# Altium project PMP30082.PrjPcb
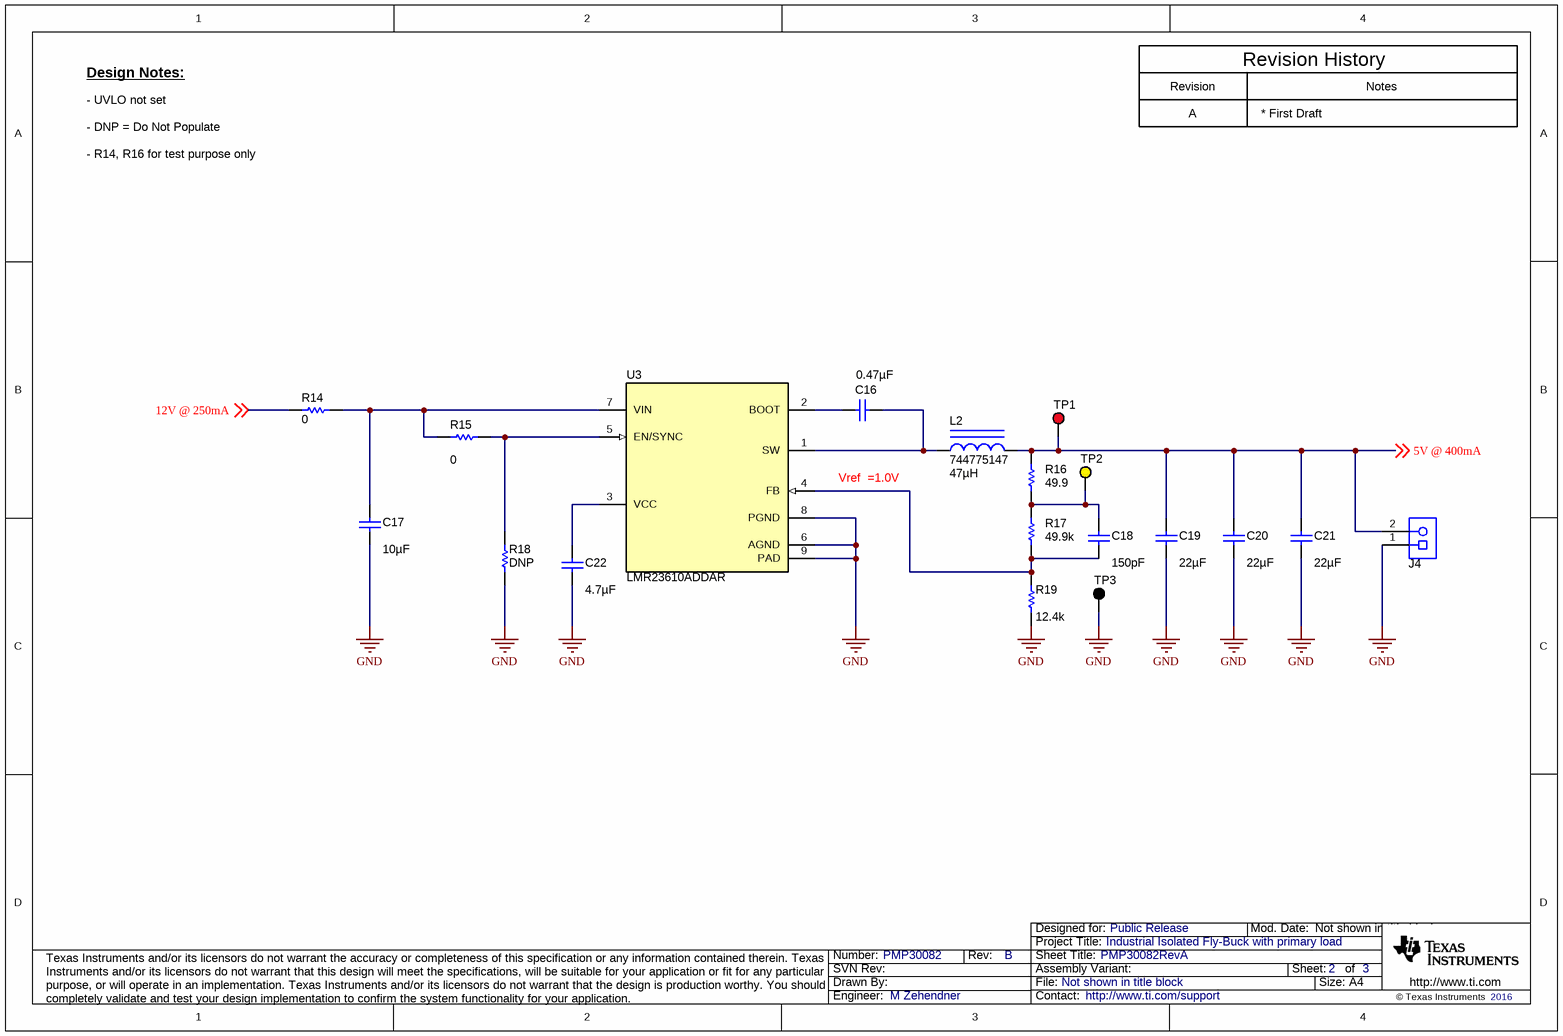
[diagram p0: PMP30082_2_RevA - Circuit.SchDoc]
CopyrightYear: 2016; EVM_Orderable: N/A; PCB_Layout: Who did the Layout?; PCB_Rev: A; PRJ_Customer: Public Release; PRJ_Engineer: M Zehendner; PRJ_Number: PMP30082; PRJ_Title: Industrial Isolated Fly-Buck with primary load; SCH_Rev: B; TechSupport: http://www.ti.com/support
3 sheets, 56 parts. Net scope: global (net labels, ports and power ports of the same name join across sheets).
Board file: PMP30082.PcbDoc
Sheets:
  PMP30082_2_RevA - Circuit.SchDoc
  PMP30082_3_RevA - Circuit.SchDoc
  PMP30082_1_RevB - Circuit.SchDoc

## Sheet PMP30082_2_RevA - Circuit.SchDoc: PMP30082RevA
size A4; Date: Not shown in title block; ApprovedBy: Not shown in title block; CheckedBy: Not shown in title block; Author: Not shown in title block; CompanyName: Not shown in title block; Engineer: Not shown in title block; Organization: Not shown in title block; Address1: Not shown in title block; Address2: Not shown in title block; Address3: Not shown in title block; Address4: Not shown in title block; DocumentNumber: 2; Revision: Use project parameter SCH_Rev; SheetNumber: 2; SheetTotal: 3; PageSetup: Record=PageOptions¦CenterHorizontal=True¦CenterVertical=True¦PrintScale=0.97¦XCorrection=1.00¦YCorrection=1.00¦PrintKind=0¦BorderSize=5000000¦LeftOffset=0¦BottomOffset=0¦Orientation=2¦PaperLength=1000¦PaperWidth=1000¦Scale=100¦PaperSource=15¦PrintQuality=600¦MediaType=1¦DitherType=10¦PaperKind=A4¦PrintScaleMode=1

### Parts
C16  ValueDisplayed: 0.47µF  [0603]  (hidden comment: GRM188R71C474KA88D)
C17  ValueDisplayed: 10µF  [0805_HV]  (hidden comment: GRM21BC71E106KE11L)
C18  ValueDisplayed: 150pF  [0603]  (hidden comment: GRM1885C2A151JA01D)
C19  ValueDisplayed: 22µF  [0805_HV]  (hidden comment: GRM21BR61A226ME44L)
C20  ValueDisplayed: 22µF  [0805_HV]  (hidden comment: GRM21BR61A226ME44L)
C21  ValueDisplayed: 22µF  [0805_HV]  (hidden comment: GRM21BR61A226ME44L)
C22  ValueDisplayed: 4.7µF  [0805_HV]  (hidden comment: GRM21BR71C475KA73L)
J4  691 101 710 002  [Wurth_691101710002]  (value not drawn)
L2  744775147  ValueDisplayed: 47µH  [WE-PD2-L]
R14  ValueDisplayed: 0  [0603]  (hidden comment: ERJ-3GEY0R00V)
R15  ValueDisplayed: 0  [0603]  (hidden comment: ERJ-3GEY0R00V)
R16  ValueDisplayed: 49.9  [0603]  (hidden comment: CRCW060349R9FKEA)
R17  ValueDisplayed: 49.9k  [0603]  (hidden comment: CRCW060349K9FKEA)
R18  ValueDisplayed: DNP  [0603]  (hidden comment: ERJ-3GEY0R00V)
R19  ValueDisplayed: 12.4k  [0603]  (hidden comment: CRCW060312K4FKEA)
TP1  5010  [Keystone5010]  (value not drawn)
TP2  5014  [Keystone5014]  (value not drawn)
TP3  5011  [Keystone5011]  (value not drawn)
U3  LMR23610ADDAR  [DDA0008E_N]

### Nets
GND: C17.2 C19.2 C20.2 C21.2 C22.2 J4.1 R18.1 R19.1 TP3.1 U3.6(AGND) U3.8(PGND) U3.9(PAD)
5V @ 400mA: C19.1 C20.1 C21.1 J4.2 L2.2 R16.2 TP1.1 ; off-sheet 5V @ 400mA
12V @ 250mA: R14.2 ; off-sheet 12V @ 250mA
NetC16_1: C16.1 L2.1 U3.1(SW)
NetC16_2: C16.2 U3.2(BOOT)
NetC17_1: C17.1 R14.1 R15.1 U3.7(VIN)
NetC18_1: C18.1 R16.1 R17.2 TP2.1
NetC18_2: C18.2 R17.1 R19.2 U3.4(FB)
NetC22_1: C22.1 U3.3(VCC)
NetR15_2: R15.2 R18.2 U3.5(EN/SYNC)

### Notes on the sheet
- Design Notes:
- - UVLO not set
- Revision
- A
- * First Draft
- Revision History
- Notes
- - DNP = Do Not Populate
- - R14, R16 for test purpose only
- Vref  =1.0V

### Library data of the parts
C16 = GRM188R71C474KA88D: CAP, CERM, 0.47 µF, 16 V, +/- 10%, X7R, 0603; Manufacturer: MuRata; Polarized: N; CompType: Capacitor; Value: 0.47uF; U/M: EA; Cap_F: 0.00000047; Tolerance_%: 10; Value1: Unknown; VDC_V: 16; Value2: 16V; TaMin_C: -55; TaMax_C: 125; SizeArea_mm2: 1.28; SizeAreaWB_mm2: 4.68; SizeX_mm: 1.6; SizeY_mm: 0.8; SizeZ_mm: 1; AEC Category: Q200
C17 = GRM21BC71E106KE11L: CAP, CERM, 10 µF, 25 V, +/- 10%, X7S, 0805; Manufacturer: MuRata; Polarized: N; CompType: Capacitor; Value: 10uF; U/M: EA; Cap_F: 0.00001; Tolerance_%: 10; Value1: Unknown; VDC_V: 25; Value2: 25V; TaMin_C: -55; TaMax_C: 125; Cap_Case: 0805; SizeArea_mm2: 2.5; SizeAreaWB_mm2: 6.75; SizeX_mm: 2; SizeY_mm: 1.25; SizeZ_mm: 1.45; AEC Category: Q200
C18 = GRM1885C2A151JA01D: CAP, CERM, 150 pF, 100 V, +/- 5%, C0G/NP0, 0603; Manufacturer: MuRata; Polarized: N; CompType: Capacitor; Value: 150pF; U/M: EA; Cap_F: 0.00000000015; Tolerance_%: 5; Value1: Unknown; VDC_V: 100; Value2: 100V; TaMin_C: -55; TaMax_C: 125; SizeArea_mm2: 1.28; SizeAreaWB_mm2: 4.68; SizeX_mm: 1.6; SizeY_mm: 0.8; SizeZ_mm: 1; AEC Category: Q200
C19-C21 = GRM21BR61A226ME44L: CAP, CERM, 22 µF, 10 V, +/- 20%, X5R, 0805; Manufacturer: MuRata; Polarized: N; CompType: Capacitor; Value: 22uF; U/M: EA; Cap_F: 0.000022; Tolerance_%: 20; Value1: Unknown; VDC_V: 10; Value2: 10V; TaMin_C: -55; TaMax_C: 85; Cap_Case: 0805; SizeArea_mm2: 2.5; SizeAreaWB_mm2: 6.75; SizeX_mm: 2; SizeY_mm: 1.25; SizeZ_mm: 1.45; AEC Category: Q200
C22 = GRM21BR71C475KA73L: CAP, CERM, 4.7 µF, 16 V, +/- 10%, X7R, 0805; Manufacturer: MuRata; Polarized: N; CompType: Capacitor; Value: 4.7uF; U/M: EA; Cap_F: 0.0000047; Tolerance_%: 10; ESR_ohm: 0.006; Value1: 0.006 ohm; VDC_V: 16; Value2: 16V; TaMin_C: -55; TaMax_C: 125; Cap_Case: 0805; SizeArea_mm2: 2.5; SizeAreaWB_mm2: 6.75; SizeX_mm: 2; SizeY_mm: 1.25; SizeZ_mm: 1.45; AEC Category: Q200
J4 = 691 101 710 002: Terminal Block, 5 mm, 2x1, Tin, TH; Manufacturer: Wurth Elektronik; SymbolCreator: a0412235
L2 = 744775147: Inductor, Shielded Drum Core, Ferrite, 47 µH, 1.17 A, 0.18 ohm, SMD; Manufacturer: Wurth Elektronik; Value: 47uH; Ind_H: 47.0E-6; Imax_A: 1.17; Irms: 1.17A @ 40C rise; Isat: 1.24A @ 10% inductance drop; DCR_ohm: 0.18; Value2: 1.17A; AEC Category: Q200
R14 R15 R18 = ERJ-3GEY0R00V: RES, 0, 5%, 0.1 W, 0603; Manufacturer: Panasonic; CompType: Resistor; Value: 0; Value_Code: 0000; Tolerance_%: 5; Power_W: 0.1; Value2: 0.1W; VDC_V: 50; TempCo: 600 ppm/C; SizeArea_mm2: 1.28; SizeX_mm: 1.6; SizeY_mm: 0.8; SizeZ_mm: 1; EIA_Code: E24; U/M: EA; AEC Category: Q200
R16 = CRCW060349R9FKEA: RES, 49.9, 1%, 0.1 W, 0603; Manufacturer: Vishay-Dale; CompType: Resistor; Value: 49.9; Value_Code: 49R9; Tolerance_%: 1; Power_W: 0.1; Value2: 0.1W; VDC_V: 75; TempCo: 100 ppm/C; SizeArea_mm2: 1.28; SizeX_mm: 1.6; SizeY_mm: 0.8; EIA_Code: E96; U/M: EA; AEC Category: Q200
R17 = CRCW060349K9FKEA: RES, 49.9 k, 1%, 0.1 W, 0603; Manufacturer: Vishay-Dale; CompType: Resistor; Value: 49.9k; Res_ohm: 49900; Value_Code: 49k9; Tolerance_%: 1; Power_W: 0.1; Value2: 0.1W; VDC_V: 75; TempCo: 100 ppm/C; SizeArea_mm2: 1.28; SizeX_mm: 1.6; SizeY_mm: 0.8; EIA_Code: E96; U/M: EA; AEC Category: Q200
R19 = CRCW060312K4FKEA: RES, 12.4 k, 1%, 0.1 W, 0603; Manufacturer: Vishay-Dale; CompType: Resistor; Value: 12.4k; Res_ohm: 12400; Value_Code: 12k4; Tolerance_%: 1; Power_W: 0.1; Value2: 0.1W; VDC_V: 75; TempCo: 100 ppm/C; SizeArea_mm2: 1.28; SizeX_mm: 1.6; SizeY_mm: 0.8; EIA_Code: E96; U/M: EA; AEC Category: Q200
TP1 = 5010: Test Point, Multipurpose, Red, TH; Manufacturer: Keystone; CompType: Test Point Loop; ContactFinish: Silver
TP2 = 5014: Test Point, Multipurpose, Yellow, TH; Manufacturer: Keystone; CompType: Test Point Loop; ContactFinish: Silver
TP3 = 5011: Test Point, Multipurpose, Black, TH; Manufacturer: Keystone; CompType: Test Point Loop; ContactFinish: Silver
U3 = LMR23610ADDAR: SIMPLE SWITCHER 36 V, 1 A Synchronous Step-Down Converter, DDA0008E; Manufacturer: Texas Instruments; SymbolCreator: a0411947; SizeArea_mm2: 31; SizeAreaWB_mm2: 57.4; SizeX_mm: 5; SizeY_mm: 6.2; SizeZ_mm: 1.7; CompType: IC; U/M: EA

## Sheet PMP30082_3_RevA - Circuit.SchDoc: PMP30082RevA
size A4; Date: Not shown in title block; ApprovedBy: Not shown in title block; CheckedBy: Not shown in title block; Author: Not shown in title block; CompanyName: Not shown in title block; Engineer: Not shown in title block; Organization: Not shown in title block; Address1: Not shown in title block; Address2: Not shown in title block; Address3: Not shown in title block; Address4: Not shown in title block; DocumentNumber: 3; Revision: Use project parameter SCH_Rev; SheetNumber: 3; SheetTotal: 3; PageSetup: Record=PageOptions¦CenterHorizontal=True¦CenterVertical=True¦PrintScale=0.97¦XCorrection=1.00¦YCorrection=1.00¦PrintKind=0¦BorderSize=5000000¦LeftOffset=0¦BottomOffset=0¦Orientation=2¦PaperLength=1000¦PaperWidth=1000¦Scale=100¦PaperSource=15¦PrintQuality=600¦MediaType=1¦DitherType=10¦PaperKind=A4¦PrintScaleMode=1
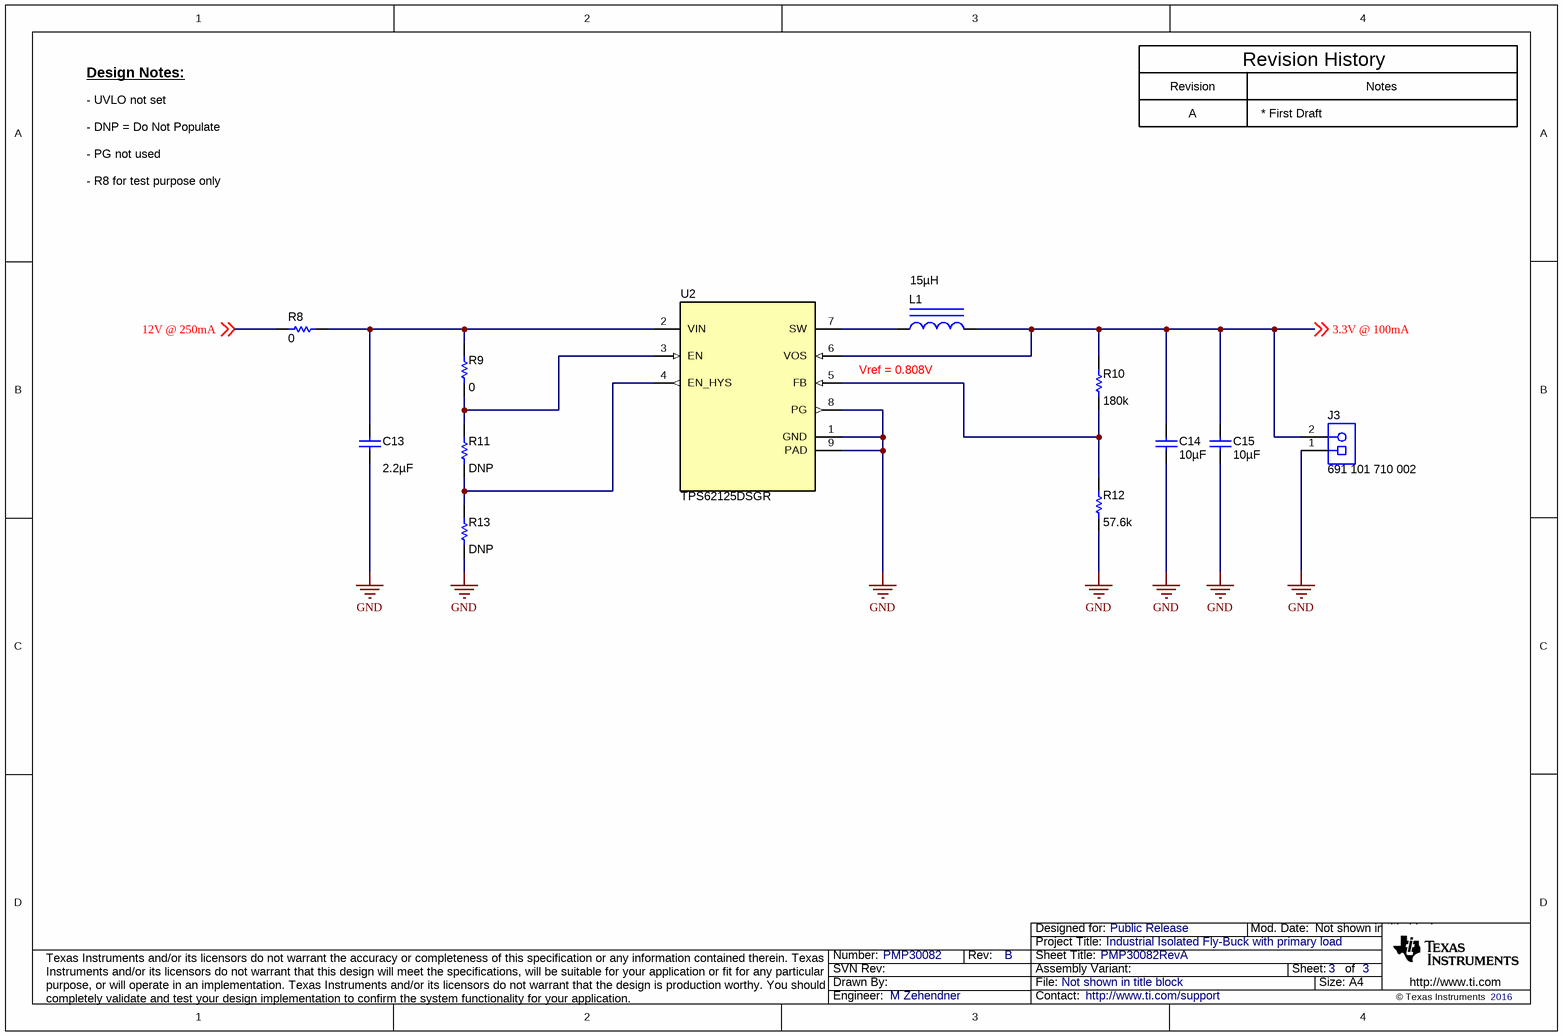
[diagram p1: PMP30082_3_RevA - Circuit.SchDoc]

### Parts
C13  ValueDisplayed: 2.2µF  [0805_HV]  (hidden comment: GRM21BR61E225KA12L)
C14  ValueDisplayed: 10µF  [0805_HV]  (hidden comment: GRM21BR70J106KE76L)
C15  ValueDisplayed: 10µF  [0805_HV]  (hidden comment: GRM21BR70J106KE76L)
J3  691 101 710 002  [Wurth_691101710002]
L1  ValueDisplayed: 15µH  [VLF302515MT]  (hidden comment: VLF302515MT-150M)
R8  ValueDisplayed: 0  [0603]  (hidden comment: ERJ-3GEY0R00V)
R9  ValueDisplayed: 0  [0603]  (hidden comment: ERJ-3GEY0R00V)
R10  ValueDisplayed: 180k  [0603]  (hidden comment: CRCW0603180KJNEA)
R11  ValueDisplayed: DNP  [0603]  (hidden comment: ERJ-3GEY0R00V)
R12  ValueDisplayed: 57.6k  [0603]  (hidden comment: CRCW060357K6FKEA)
R13  ValueDisplayed: DNP  [0603]  (hidden comment: ERJ-3GEY0R00V)
U2  TPS62125DSGR  [DSG0008A]

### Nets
GND: C13.2 C14.2 C15.2 J3.1 R12.1 R13.1 U2.1(GND) U2.8(PG) U2.9(PAD)
3.3V @ 100mA: C14.1 C15.1 J3.2 L1.2 R10.2 U2.6(VOS) ; off-sheet 3.3V @ 100mA
12V @ 250mA: R8.2 ; off-sheet 12V @ 250mA
NetC13_1: C13.1 R8.1 R9.2 U2.2(VIN)
NetL1_1: L1.1 U2.7(SW)
NetR9_1: R9.1 R11.2 U2.3(EN)
NetR10_1: R10.1 R12.2 U2.5(FB)
NetR11_1: R11.1 R13.2 U2.4(EN_HYS)

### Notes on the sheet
- Design Notes:
- - UVLO not set
- Revision
- A
- * First Draft
- Revision History
- Notes
- - DNP = Do Not Populate
- - PG not used
- - R8 for test purpose only
- Vref = 0.808V

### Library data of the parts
C13 = GRM21BR61E225KA12L: CAP, CERM, 2.2 µF, 25 V, +/- 10%, X5R, 0805; Manufacturer: MuRata; Polarized: N; CompType: Capacitor; Value: 2.2uF; U/M: EA; Cap_F: 0.0000022; Tolerance_%: 10; ESR_ohm: 0.008; Value1: 0.008 ohm; VDC_V: 25; Value2: 25V; TaMin_C: -55; TaMax_C: 85; Cap_Case: 0805; SizeArea_mm2: 2.5; SizeAreaWB_mm2: 6.75; SizeX_mm: 2; SizeY_mm: 1.25; SizeZ_mm: 1.45; AEC Category: Q200
C14 C15 = GRM21BR70J106KE76L: CAP, CERM, 10 µF, 6.3 V, +/- 10%, X7R, 0805; Manufacturer: MuRata; Polarized: N; CompType: Capacitor; Value: 10uF; U/M: EA; Cap_F: 0.00001; Tolerance_%: 10; Value1: Unknown; VDC_V: 6.3; Value2: 6.3V; TaMin_C: -55; TaMax_C: 125; Cap_Case: 0805; SizeArea_mm2: 2.5; SizeAreaWB_mm2: 6.75; SizeX_mm: 2; SizeY_mm: 1.25; SizeZ_mm: 1.45; AEC Category: Q200
J3 = 691 101 710 002: as J4 on sheet PMP30082_2_RevA - Circuit
L1 = VLF302515MT-150M: Inductor, Shielded, Ferrite, 15 µH, 0.56 A, 0.275 ohm, SMD; Manufacturer: TDK; Value: 15uH; Ind_H: 15.0E-6; Imax_A: 0.56; Irms: 0.99A @ 40C rise; Isat: 0.56A @ 30% inductance drop; DCR_ohm: 0.275; Value2: 0.56A; AEC Category: Q200
R8 R9 R11 R13 = ERJ-3GEY0R00V: as R14 on sheet PMP30082_2_RevA - Circuit
R10 = CRCW0603180KJNEA: RES, 180 k, 5%, 0.1 W, 0603; Manufacturer: Vishay-Dale; CompType: Resistor; Value: 180k; Res_ohm: 180000; Tolerance_%: 5; Power_W: 0.1; Value2: 0.1W; VDC_V: 75; TempCo: 200 ppm/C; SizeArea_mm2: 1.28; SizeX_mm: 1.6; SizeY_mm: 0.8; SizeZ_mm: 1; EIA_Code: E24; U/M: EA; AEC Category: Q200
R12 = CRCW060357K6FKEA: RES, 57.6 k, 1%, 0.1 W, 0603; Manufacturer: Vishay-Dale; CompType: Resistor; Value: 57.6k; Res_ohm: 57600; Value_Code: 57k6; Tolerance_%: 1; Power_W: 0.1; Value2: 0.1W; VDC_V: 75; TempCo: 100 ppm/C; SizeArea_mm2: 1.28; SizeX_mm: 1.6; SizeY_mm: 0.8; EIA_Code: E96; U/M: EA; AEC Category: Q200
U2 = TPS62125DSGR: 3V-17V, 300mA Step Down Converter With Adjustable Enable Threshold And Hysteresis, DSG0008A; Alternate PartNumber: TPS62125DSGT; Manufacturer: Texas Instruments; SymbolCreator: a0412235; SizeArea_mm2: 4; SizeAreaWB_mm2: 9; SizeX_mm: 2; SizeZ_mm: 0.8; CompType: IC; U/M: EA

## Sheet PMP30082_1_RevB - Circuit.SchDoc: PMP30082RevB
size A4; Date: Not shown in title block; ApprovedBy: Not shown in title block; CheckedBy: Not shown in title block; Author: Not shown in title block; CompanyName: Not shown in title block; Engineer: Not shown in title block; Organization: Not shown in title block; Address1: Not shown in title block; Address2: Not shown in title block; Address3: Not shown in title block; Address4: Not shown in title block; DocumentNumber: 1; Revision: Use project parameter SCH_Rev; SheetNumber: 1; SheetTotal: 3; PageSetup: Record=PageOptions¦CenterHorizontal=True¦CenterVertical=True¦PrintScale=0.97¦XCorrection=1.00¦YCorrection=1.00¦PrintKind=0¦BorderSize=5000000¦LeftOffset=0¦BottomOffset=0¦Orientation=2¦PaperLength=1000¦PaperWidth=1000¦Scale=100¦PaperSource=15¦PrintQuality=600¦MediaType=1¦DitherType=10¦PaperKind=A4¦PrintScaleMode=1
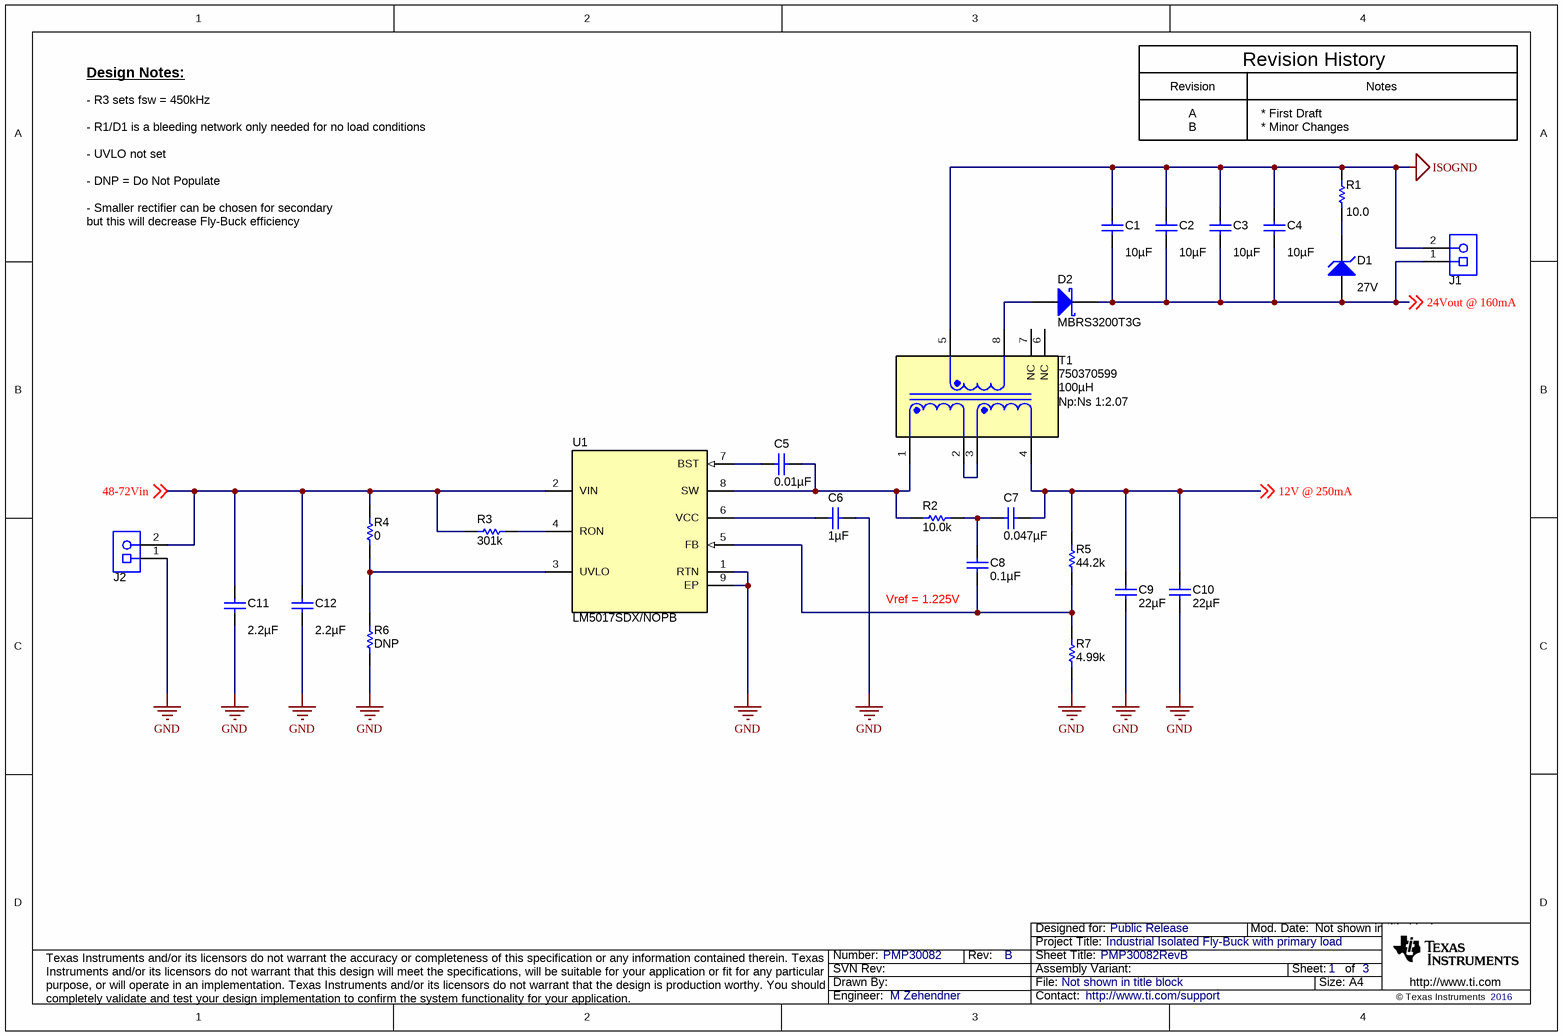
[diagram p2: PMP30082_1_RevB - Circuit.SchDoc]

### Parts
C1  ValueDisplayed: 10µF  [1210_270]  (hidden comment: GRM32ER61H106KA12L)
C2  ValueDisplayed: 10µF  [1210_270]  (hidden comment: GRM32ER61H106KA12L)
C3  ValueDisplayed: 10µF  [1210_270]  (hidden comment: GRM32ER61H106KA12L)
C4  ValueDisplayed: 10µF  [1210_270]  (hidden comment: GRM32ER61H106KA12L)
C5  ValueDisplayed: 0.01µF  [0603]  (hidden comment: GCM188R71H103KA37D)
C6  ValueDisplayed: 1µF  [0603]  (hidden comment: GRM188R71C105KA12D)
C7  ValueDisplayed: 0.047µF  [0603]  (hidden comment: GRM188R70J473KA01D)
C8  ValueDisplayed: 0.1µF  [0603]  (hidden comment: GCM188R71H104KA57D)
C9  ValueDisplayed: 22µF  [1210_270]  (hidden comment: GRM32ER61E226KE15L)
C10  ValueDisplayed: 22µF  [1210_270]  (hidden comment: GRM32ER61E226KE15L)
C11  ValueDisplayed: 2.2µF  [1210_270]  (hidden comment: GRM32ER72A225KA35L)
C12  ValueDisplayed: 2.2µF  [1210_270]  (hidden comment: GRM32ER72A225KA35L)
D1  value 27V  [SOD-123]  (hidden comment: MMSZ5254B-7-F)
D2  MBRS3200T3G  [SMB]
J1  691 101 710 002  [Wurth_691101710002]  (value not drawn)
J2  691 101 710 002  [Wurth_691101710002]  (value not drawn)
R1  ValueDisplayed: 10.0  [0603]  (hidden comment: CRCW060310R0FKEA)
R2  ValueDisplayed: 10.0k  [0603]  (hidden comment: CRCW060310K0FKEA)
R3  ValueDisplayed: 301k  [0603]  (hidden comment: CRCW0603301KFKEA)
R4  ValueDisplayed: 0  [0603]  (hidden comment: ERJ-3GEY0R00V)
R5  ValueDisplayed: 44.2k  [0603]  (hidden comment: CRCW060344K2FKEA)
R6  ValueDisplayed: DNP  [0603]  (hidden comment: CRCW060310K0FKEA)
R7  ValueDisplayed: 4.99k  [0603]  (hidden comment: CPF0603B4K99E)
T1  750370599  ValueDisplayed: 100µH  [Wurth_750370599]
U1  LM5017SDX/NOPB  [NGU0008B]

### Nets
GND: C6.1 C9.2 C10.2 C11.2 C12.2 J2.1 R6.1 R7.1 U1.1(RTN) U1.9(EP)
ISOGND: C1.1 C2.1 C3.1 C4.1 J1.2 R1.2 T1.5
12V @ 250mA: C7.1 C9.1 C10.1 R5.2 T1.4 ; off-sheet 12V @ 250mA
24Vout @ 160mA: C1.2 C2.2 C3.2 C4.2 D1.2(A) D2.1(K) J1.1 ; off-sheet 24Vout @ 160mA
48-72Vin: C11.1 C12.1 J2.2 R3.1 R4.2 U1.2(VIN) ; off-sheet 48-72Vin
NetC5_1: C5.1 R2.1 T1.1 U1.8(SW)
NetC5_2: C5.2 U1.7(BST)
NetC6_2: C6.2 U1.6(VCC)
NetC7_2: C7.2 C8.1 R2.2
NetC8_2: C8.2 R5.1 R7.2 U1.5(FB)
NetD1_1: D1.1(K) R1.1
NetD2_2: D2.2(A) T1.8
NetR3_2: R3.2 U1.4(RON)
NetR4_1: R4.1 R6.2 U1.3(UVLO)
NetT1_2: T1.2 T1.3

Not connected (* = marked no-connect by the designer): T1 6(NC) 7(NC)

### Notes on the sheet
- Design Notes:
- - R3 sets fsw = 450kHz
- Revision
- A
- * First Draft
- Revision History
- Notes
- - R1/D1 is a bleeding network only needed for no load conditions
- - UVLO not set
- - DNP = Do Not Populate
- B
- (near R1) * Minor Changes
- - Smaller rectifier can be chosen for secondary
- but this will decrease Fly-Buck efficiency
- (near T1) Np:Ns 1:2.07
- (near C8) Vref = 1.225V

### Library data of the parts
C1-C4 = GRM32ER61H106KA12L: CAP, CERM, 10 µF, 50 V, +/- 10%, X5R, 1210; Manufacturer: MuRata; Polarized: N; CompType: Capacitor; Value: 10uF; U/M: EA; Cap_F: 0.00001; Tolerance_%: 10; Value1: Unknown; VDC_V: 50; Value2: 50V; TaMin_C: -55; TaMax_C: 85; Cap_Case: 1210; SizeArea_mm2: 8; SizeAreaWB_mm2: 14.7; SizeX_mm: 3.2; SizeY_mm: 2.5; SizeZ_mm: 2.7; AEC Category: Q200
C5 = GCM188R71H103KA37D: CAP, CERM, 0.01 µF, 50 V, +/- 10%, X7R, AEC-Q200 Grade 1, 0603; Manufacturer: MuRata; Polarized: N; CompType: Capacitor; Value: 0.01uF; U/M: EA; Cap_F: 0.00000001; Tolerance_%: 10; Value1: Unknown; VDC_V: 50; Value2: 50V; TaMin_C: -55; TaMax_C: 125; AEC Category: Q200; AEC Qualified: Y; AEC Grade: 1
C6 = GRM188R71C105KA12D: CAP, CERM, 1 µF, 16 V, +/- 10%, X7R, 0603; Manufacturer: MuRata; Polarized: N; CompType: Capacitor; Value: 1uF; U/M: EA; Cap_F: 0.000001; Tolerance_%: 10; ESR_ohm: 0.011; Value1: 0.011 ohm; VDC_V: 16; Value2: 16V; TaMin_C: -55; TaMax_C: 125; SizeArea_mm2: 1.28; SizeAreaWB_mm2: 4.68; SizeX_mm: 1.6; SizeY_mm: 0.8; SizeZ_mm: 1; AEC Category: Q200
C7 = GRM188R70J473KA01D: CAP, CERM, 0.047 µF, 6.3 V, +/- 10%, X7R, 0603; Manufacturer: MuRata; Polarized: N; CompType: Capacitor; Value: 0.047uF; U/M: EA; Cap_F: 0.000000047; Tolerance_%: 10; Value1: Unknown; VDC_V: 6.3; Value2: 6.3V; TaMin_C: -55; TaMax_C: 125; SizeArea_mm2: 1.28; SizeAreaWB_mm2: 4.68; SizeX_mm: 1.6; SizeY_mm: 0.8; SizeZ_mm: 1; AEC Category: Q200
C8 = GCM188R71H104KA57D: CAP, CERM, 0.1 µF, 50 V, +/- 10%, X7R, 0603; Manufacturer: MuRata; Polarized: N; CompType: Capacitor; Value: 0.1uF; U/M: EA; Cap_F: 0.0000001; Tolerance_%: 10; ESR_ohm: 0.02; Value1: 0.02 ohm; VDC_V: 50; Value2: 50V; IRMS_A: 1.84; TaMin_C: -55; TaMax_C: 125; AEC Category: Q200; SizeArea_mm2: 1.28; SizeAreaWB_mm2: 4.68; SizeX_mm: 1.6; SizeY_mm: 0.8; SizeZ_mm: 1
C9 C10 = GRM32ER61E226KE15L: CAP, CERM, 22 µF, 25 V, +/- 10%, X5R, 1210; Manufacturer: MuRata; Polarized: N; CompType: Capacitor; Value: 22uF; U/M: EA; Cap_F: 0.000022; Tolerance_%: 10; ESR_ohm: 0.002; Value1: 0.002 ohm; VDC_V: 25; Value2: 25V; IRMS_A: 3.67; TaMin_C: -55; TaMax_C: 85; Cap_Case: 1210; SizeArea_mm2: 8; SizeAreaWB_mm2: 14.7; SizeX_mm: 3.2; SizeY_mm: 2.5; SizeZ_mm: 2.7; AEC Category: Q200
C11 C12 = GRM32ER72A225KA35L: CAP, CERM, 2.2 µF, 100 V, +/- 10%, X7R, 1210; Manufacturer: MuRata; Polarized: N; CompType: Capacitor; Value: 2.2uF; U/M: EA; Cap_F: 0.0000022; Tolerance_%: 10; ESR_ohm: 0.007; Value1: 0.007 ohm; VDC_V: 100; Value2: 100V; IRMS_A: 4.4; TaMin_C: -55; TaMax_C: 125; Cap_Case: 1210; SizeArea_mm2: 8; SizeAreaWB_mm2: 14.7; SizeX_mm: 3.2; SizeY_mm: 2.5; SizeZ_mm: 2.7; AEC Category: Q200
D1 = MMSZ5254B-7-F: Diode, Zener, 27 V, 500 mW, SOD-123; Manufacturer: Diodes Inc.; SymbolCreator: a0412235; U/M: EA; Power_W: 0.5; Vz_V: 27; Value1: 0.5W; RJA_CperW: 350; SizeAreaWB_mm2: 13.095; SizeArea_mm2: 6.545; SizeX_mm: 3.85; SizeY_mm: 1.7; SizeZ_mm: 1.35; AEC Category: Q101
D2 = MBRS3200T3G: Diode, Schottky, 200 V, 3 A, SMB; Manufacturer: ON Semiconductor; U/M: EA; Vf_V: 0.84; Value: 200V; Value1: 3A; Value2: 0.84V; Io_A: 3; Vr_V: 200; TJmax_C: 175; RJC_CperW: 62; SizeAreaWB_mm2: 44.156; SizeArea_mm2: 21.336; SizeX_mm: 5.6; SizeY_mm: 3.81; SizeZ_mm: 2.6; AEC Category: Q101
J1 J2 = 691 101 710 002: as J4 on sheet PMP30082_2_RevA - Circuit
R1 = CRCW060310R0FKEA: RES, 10.0, 1%, 0.1 W, 0603; Manufacturer: Vishay-Dale; CompType: Resistor; Value: 10.0; Res_ohm: 10; Value_Code: 10R0; Tolerance_%: 1; Power_W: 0.1; Value2: 0.1W; VDC_V: 75; TempCo: 100 ppm/C; SizeArea_mm2: 1.28; SizeX_mm: 1.6; SizeY_mm: 0.8; EIA_Code: E96; U/M: EA; AEC Category: Q200
R2 = CRCW060310K0FKEA: RES, 10.0 k, 1%, 0.1 W, 0603; Manufacturer: Vishay-Dale; CompType: Resistor; Value: 10.0k; Res_ohm: 10000; Value_Code: 10k0; Tolerance_%: 1; Power_W: 0.1; Value2: 0.1W; VDC_V: 75; TempCo: 100 ppm/C; SizeArea_mm2: 1.28; SizeX_mm: 1.6; SizeY_mm: 0.8; EIA_Code: E96; U/M: EA; AEC Category: Q200
R3 = CRCW0603301KFKEA: RES, 301 k, 1%, 0.1 W, 0603; Manufacturer: Vishay-Dale; CompType: Resistor; Value: 301k; Res_ohm: 301000; Tolerance_%: 1; Power_W: 0.1; Value2: 0.1W; VDC_V: 75; TempCo: 100 ppm/C; EIA_Code: E96; U/M: EA; AEC Category: Q200; SizeArea_mm2: 1.28; SizeX_mm: 1.6; SizeY_mm: 0.8
R4 = ERJ-3GEY0R00V: RES, 0, 5%, 0.1 W, 0603; Manufacturer: Panasonic; CompType: Resistor; Value: 0; Value_Code: 0000; Tolerance_%: 5; Power_W: 0.1; Value2: 0.1W; VDC_V: 50; TempCo: 600 ppm/C; EIA_Code: E24; U/M: EA; AEC Category: Q200; SizeArea_mm2: 1.28; SizeX_mm: 1.6; SizeY_mm: 0.8; SizeZ_mm: 1
R5 = CRCW060344K2FKEA: RES, 44.2 k, 1%, 0.1 W, 0603; Manufacturer: Vishay-Dale; CompType: Resistor; Value: 44.2k; Res_ohm: 44200; Value_Code: 44k2; Tolerance_%: 1; Power_W: 0.1; Value2: 0.1W; VDC_V: 75; TempCo: 100 ppm/C; SizeArea_mm2: 1.28; SizeX_mm: 1.6; SizeY_mm: 0.8; EIA_Code: E96; U/M: EA; AEC Category: Q200
R6 = CRCW060310K0FKEA: RES, 10.0 k, 1%, 0.1 W, 0603; Manufacturer: Vishay-Dale; CompType: Resistor; Value: 10.0k; Res_ohm: 10000; Value_Code: 10k0; Tolerance_%: 1; Power_W: 0.1; Value2: 0.1W; VDC_V: 75; TempCo: 100 ppm/C; EIA_Code: E96; U/M: EA; AEC Category: Q200
R7 = CPF0603B4K99E: RES, 4.99 k, 0.1%, 0.063 W, 0603; Manufacturer: TE Connectivity; CompType: Resistor; Value: 4.99k; Res_ohm: 4990; Value_Code: 4k99; Tolerance_%: 0.1; Power_W: 0.063; Value2: 0.063W; VDC_V: 50; TempCo: 25 ppm/C; SizeArea_mm2: 1.28; SizeX_mm: 1.6; SizeY_mm: 0.8; SizeZ_mm: 1; EIA_Code: E192; U/M: EA; AEC Category: Q200
T1 = 750370599: Transformer, 250 uH, SMT; Manufacturer: Wurth Elektronik; SymbolCreator: Altium; Value: 250uH; Lp: 250; DCR_ohm: 0.163; LeakageL: 0.7; SizeAreaWB_mm2: 264.4616; SizeArea_mm2: 203.3016; SizeX_mm: 13.34; SizeY_mm: 15.24; SizeZ_mm: 11.43
U1 = LM5017SDX/NOPB: 100V, 600mA Constant On-Time Synchronous Buck Regulator, NGU0008B; Alternate PartNumber: LM5017SD/NOPB; Manufacturer: Texas Instruments; SymbolCreator: a0412235; SizeX_mm: 4; SizeZ_mm: 0.8; CompType: IC; U/M: EA

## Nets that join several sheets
GND: PMP30082_2_RevA - Circuit (12 pins), PMP30082_3_RevA - Circuit (9 pins), PMP30082_1_RevB - Circuit (10 pins)
12V @ 250mA: PMP30082_2_RevA - Circuit (R14.2), PMP30082_3_RevA - Circuit (R8.2), PMP30082_1_RevB - Circuit (5 pins)

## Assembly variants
001: not fitted FID1 FID2 FID3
